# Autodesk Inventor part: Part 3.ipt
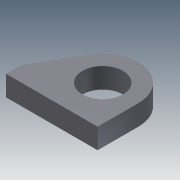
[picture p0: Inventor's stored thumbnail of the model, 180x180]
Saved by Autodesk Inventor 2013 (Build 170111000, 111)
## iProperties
Created: 2005-04
Part Number: Part 3.ipt
Material: Steel, Mild
Document SubType Name: Modeling
Designer: salex
Manufacturer: Standard
Standards Organization: Custom
Density: 7.86 g/cm^3
Author: salex
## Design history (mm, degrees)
sketch "Эскиз1"
  geometry: L1 (275.476, 609.23)-(185.476, 609.23); L2 (185.476, 609.23)-(185.476, 624.23); L3 (185.476, 624.23)-(210.212, 666.811); L4 (275.476, 649.23)-(275.476, 609.23); C1 r 20 at (240.476, 649.23); A1 r 35 centre (240.476, 649.23) between (275.476, 649.23) and (210.212, 666.811)
  constraints: 8 end point, 2 centre point, 2 point on circle, 2 tangent, 1 concentric, 1 horizontal, 1 parallel, 1 perpendicular, 1 other
  dimensions: "d0" = 15 distance from line of L2.end L1; "d1" = 90 distance of L1.start L1.end; "d2" = 40 distance from line of C1.centre L1; "d3" = 40 diameter of C1; "d4" = 35 radius of A1
extrude "Выдавливание1" new body sketch "Эскиз1" distance "d6" = 20; taper "d7" = 0 deg
body "Solid1"
